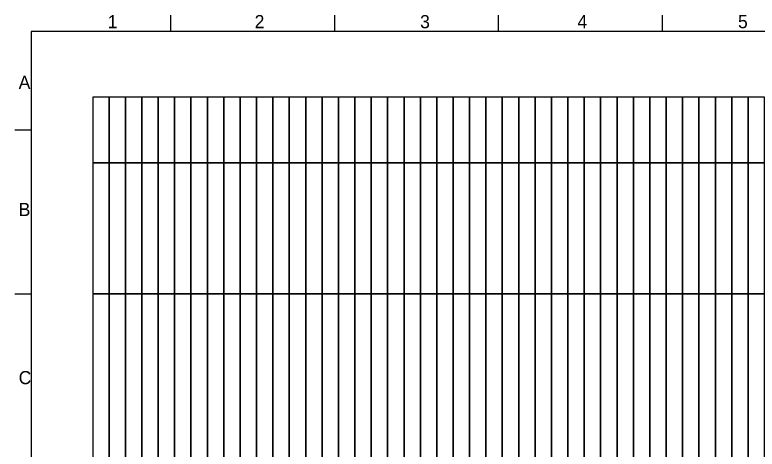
# Model space of a CAD drawing. Extents: x 0 to 395, y 0 to 270.
# Drawn here: x 0 to 226.5, y 137.7 to 270.1 of the extents above; entities that cross this region are included whole.
import ezdxf

# ---------------------------------------------------------------- set-up
doc = ezdxf.new("R2010")
doc.units = 0
doc.layers.add('30_Graphik', color=7, linetype='Continuous')
doc.layers.add('90_Plankopf', color=7, linetype='Continuous')

msp = doc.modelspace()

# ---------------------------------------------------------------- linework, layer by layer
at = {"layer": '30_Graphik'}
for points in [[(23.75, 245), (23.75, 225), (28.75, 225), (28.75, 245)], [(28.75, 245), (28.75, 225), (33.75, 225), (33.75, 245)], [(33.75, 245), (33.75, 225), (38.75, 225), (38.75, 245)], [(38.75, 245), (38.75, 225), (43.75, 225), (43.75, 245)], [(43.75, 245), (43.75, 225), (48.75, 225), (48.75, 245)], [(48.75, 245), (48.75, 225), (53.75, 225), (53.75, 245)], [(53.75, 245), (53.75, 225), (58.75, 225), (58.75, 245)], [(58.75, 245), (58.75, 225), (63.75, 225), (63.75, 245)], [(63.75, 245), (63.75, 225), (68.75, 225), (68.75, 245)], [(68.75, 245), (68.75, 225), (73.75, 225), (73.75, 245)], [(73.75, 245), (73.75, 225), (78.75, 225), (78.75, 245)], [(78.75, 245), (78.75, 225), (83.75, 225), (83.75, 245)], [(83.75, 245), (83.75, 225), (88.75, 225), (88.75, 245)], [(88.75, 245), (88.75, 225), (93.75, 225), (93.75, 245)], [(93.75, 245), (93.75, 225), (98.75, 225), (98.75, 245)], [(98.75, 245), (98.75, 225), (103.75, 225), (103.75, 245)], [(103.75, 245), (103.75, 225), (108.75, 225), (108.75, 245)], [(108.75, 245), (108.75, 225), (113.75, 225), (113.75, 245)], [(113.75, 245), (113.75, 225), (118.75, 225), (118.75, 245)], [(118.75, 245), (118.75, 225), (123.75, 225), (123.75, 245)], [(123.75, 245), (123.75, 225), (128.75, 225), (128.75, 245)], [(128.75, 245), (128.75, 225), (133.75, 225), (133.75, 245)], [(133.75, 245), (133.75, 225), (138.75, 225), (138.75, 245)], [(138.75, 245), (138.75, 225), (143.75, 225), (143.75, 245)], [(143.75, 245), (143.75, 225), (148.75, 225), (148.75, 245)], [(148.75, 245), (148.75, 225), (153.75, 225), (153.75, 245)], [(153.75, 245), (153.75, 225), (158.75, 225), (158.75, 245)], [(158.75, 245), (158.75, 225), (163.75, 225), (163.75, 245)], [(163.75, 245), (163.75, 225), (168.75, 225), (168.75, 245)], [(168.75, 245), (168.75, 225), (173.75, 225), (173.75, 245)], [(173.75, 245), (173.75, 225), (178.75, 225), (178.75, 245)], [(178.75, 245), (178.75, 225), (183.75, 225), (183.75, 245)], [(183.75, 245), (183.75, 225), (188.75, 225), (188.75, 245)], [(188.75, 245), (188.75, 225), (193.75, 225), (193.75, 245)], [(193.75, 245), (193.75, 225), (198.75, 225), (198.75, 245)], [(198.75, 245), (198.75, 225), (203.75, 225), (203.75, 245)], [(203.75, 245), (203.75, 225), (208.75, 225), (208.75, 245)], [(208.75, 245), (208.75, 225), (213.75, 225), (213.75, 245)], [(213.75, 245), (213.75, 225), (218.75, 225), (218.75, 245)], [(218.75, 245), (218.75, 225), (223.75, 225), (223.75, 245)], [(223.75, 245), (223.75, 225), (228.75, 225), (228.75, 245)], [(23.75, 225), (23.75, 185), (28.75, 185), (28.75, 225)], [(28.75, 225), (28.75, 185), (33.75, 185), (33.75, 225)], [(33.75, 225), (33.75, 185), (38.75, 185), (38.75, 225)], [(38.75, 225), (38.75, 185), (43.75, 185), (43.75, 225)], [(43.75, 225), (43.75, 185), (48.75, 185), (48.75, 225)], [(48.75, 225), (48.75, 185), (53.75, 185), (53.75, 225)], [(53.75, 225), (53.75, 185), (58.75, 185), (58.75, 225)], [(58.75, 225), (58.75, 185), (63.75, 185), (63.75, 225)], [(63.75, 225), (63.75, 185), (68.75, 185), (68.75, 225)], [(68.75, 225), (68.75, 185), (73.75, 185), (73.75, 225)], [(73.75, 225), (73.75, 185), (78.75, 185), (78.75, 225)], [(78.75, 225), (78.75, 185), (83.75, 185), (83.75, 225)], [(83.75, 225), (83.75, 185), (88.75, 185), (88.75, 225)], [(88.75, 225), (88.75, 185), (93.75, 185), (93.75, 225)], [(93.75, 225), (93.75, 185), (98.75, 185), (98.75, 225)], [(98.75, 225), (98.75, 185), (103.75, 185), (103.75, 225)], [(103.75, 225), (103.75, 185), (108.75, 185), (108.75, 225)], [(108.75, 225), (108.75, 185), (113.75, 185), (113.75, 225)], [(113.75, 225), (113.75, 185), (118.75, 185), (118.75, 225)], [(118.75, 225), (118.75, 185), (123.75, 185), (123.75, 225)], [(123.75, 225), (123.75, 185), (128.75, 185), (128.75, 225)], [(128.75, 225), (128.75, 185), (133.75, 185), (133.75, 225)], [(133.75, 225), (133.75, 185), (138.75, 185), (138.75, 225)], [(138.75, 225), (138.75, 185), (143.75, 185), (143.75, 225)], [(143.75, 225), (143.75, 185), (148.75, 185), (148.75, 225)], [(148.75, 225), (148.75, 185), (153.75, 185), (153.75, 225)], [(153.75, 225), (153.75, 185), (158.75, 185), (158.75, 225)], [(158.75, 225), (158.75, 185), (163.75, 185), (163.75, 225)], [(163.75, 225), (163.75, 185), (168.75, 185), (168.75, 225)], [(168.75, 225), (168.75, 185), (173.75, 185), (173.75, 225)], [(173.75, 225), (173.75, 185), (178.75, 185), (178.75, 225)], [(178.75, 225), (178.75, 185), (183.75, 185), (183.75, 225)], [(183.75, 225), (183.75, 185), (188.75, 185), (188.75, 225)], [(188.75, 225), (188.75, 185), (193.75, 185), (193.75, 225)], [(193.75, 225), (193.75, 185), (198.75, 185), (198.75, 225)], [(198.75, 225), (198.75, 185), (203.75, 185), (203.75, 225)], [(203.75, 225), (203.75, 185), (208.75, 185), (208.75, 225)], [(208.75, 225), (208.75, 185), (213.75, 185), (213.75, 225)], [(213.75, 225), (213.75, 185), (218.75, 185), (218.75, 225)], [(218.75, 225), (218.75, 185), (223.75, 185), (223.75, 225)], [(223.75, 225), (223.75, 185), (228.75, 185), (228.75, 225)], [(23.75, 185), (23.75, 90), (28.75, 90), (28.75, 185)], [(28.75, 185), (28.75, 90), (33.75, 90), (33.75, 185)], [(33.75, 185), (33.75, 90), (38.75, 90), (38.75, 185)], [(38.75, 185), (38.75, 90), (43.75, 90), (43.75, 185)], [(43.75, 185), (43.75, 90), (48.75, 90), (48.75, 185)], [(48.75, 185), (48.75, 90), (53.75, 90), (53.75, 185)], [(53.75, 185), (53.75, 90), (58.75, 90), (58.75, 185)], [(58.75, 185), (58.75, 90), (63.75, 90), (63.75, 185)], [(63.75, 185), (63.75, 90), (68.75, 90), (68.75, 185)], [(68.75, 185), (68.75, 90), (73.75, 90), (73.75, 185)], [(73.75, 185), (73.75, 90), (78.75, 90), (78.75, 185)], [(78.75, 185), (78.75, 90), (83.75, 90), (83.75, 185)], [(83.75, 185), (83.75, 90), (88.75, 90), (88.75, 185)], [(88.75, 185), (88.75, 90), (93.75, 90), (93.75, 185)], [(93.75, 185), (93.75, 90), (98.75, 90), (98.75, 185)], [(98.75, 185), (98.75, 90), (103.75, 90), (103.75, 185)], [(103.75, 185), (103.75, 90), (108.75, 90), (108.75, 185)], [(108.75, 185), (108.75, 90), (113.75, 90), (113.75, 185)], [(113.75, 185), (113.75, 90), (118.75, 90), (118.75, 185)], [(118.75, 185), (118.75, 90), (123.75, 90), (123.75, 185)], [(123.75, 185), (123.75, 90), (128.75, 90), (128.75, 185)], [(128.75, 185), (128.75, 90), (133.75, 90), (133.75, 185)], [(133.75, 185), (133.75, 90), (138.75, 90), (138.75, 185)], [(138.75, 185), (138.75, 90), (143.75, 90), (143.75, 185)], [(143.75, 185), (143.75, 90), (148.75, 90), (148.75, 185)], [(148.75, 185), (148.75, 90), (153.75, 90), (153.75, 185)], [(153.75, 185), (153.75, 90), (158.75, 90), (158.75, 185)], [(158.75, 185), (158.75, 90), (163.75, 90), (163.75, 185)], [(163.75, 185), (163.75, 90), (168.75, 90), (168.75, 185)], [(168.75, 185), (168.75, 90), (173.75, 90), (173.75, 185)], [(173.75, 185), (173.75, 90), (178.75, 90), (178.75, 185)], [(178.75, 185), (178.75, 90), (183.75, 90), (183.75, 185)], [(183.75, 185), (183.75, 90), (188.75, 90), (188.75, 185)], [(188.75, 185), (188.75, 90), (193.75, 90), (193.75, 185)], [(193.75, 185), (193.75, 90), (198.75, 90), (198.75, 185)], [(198.75, 185), (198.75, 90), (203.75, 90), (203.75, 185)], [(203.75, 185), (203.75, 90), (208.75, 90), (208.75, 185)], [(208.75, 185), (208.75, 90), (213.75, 90), (213.75, 185)], [(213.75, 185), (213.75, 90), (218.75, 90), (218.75, 185)], [(218.75, 185), (218.75, 90), (223.75, 90), (223.75, 185)], [(223.75, 185), (223.75, 90), (228.75, 90), (228.75, 185)]]:
    msp.add_lwpolyline(points, close=True, dxfattribs=at)
at = {"layer": '90_Plankopf'}
for p, q in [((47.5, 270), (47.5, 265)), ((97.5, 270), (97.5, 265)), ((147.5, 270), (147.5, 265)), ((197.5, 270), (197.5, 265)), ((390, 265), (5, 265)), ((5, 265), (5, 5)), ((0, 235), (5, 235)), ((0, 185), (5, 185))]:
    msp.add_line(p, q, dxfattribs=at)

# ---------------------------------------------------------------- texts
for s, p in [('1', (28.33, 266)), ('2', (73.17, 266)), ('3', (123.67, 266)), ('4', (171.67, 266)), ('5', (220.67, 266)), ('A', (1.17, 247.5)), ('B', (1.17, 208.75)), ('C', (1.17, 157.5))]:
    msp.add_text(s, height=4, dxfattribs=at).set_placement(p)

doc.saveas('drawing.dxf')
